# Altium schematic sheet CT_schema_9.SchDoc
size 277 x 170 mm
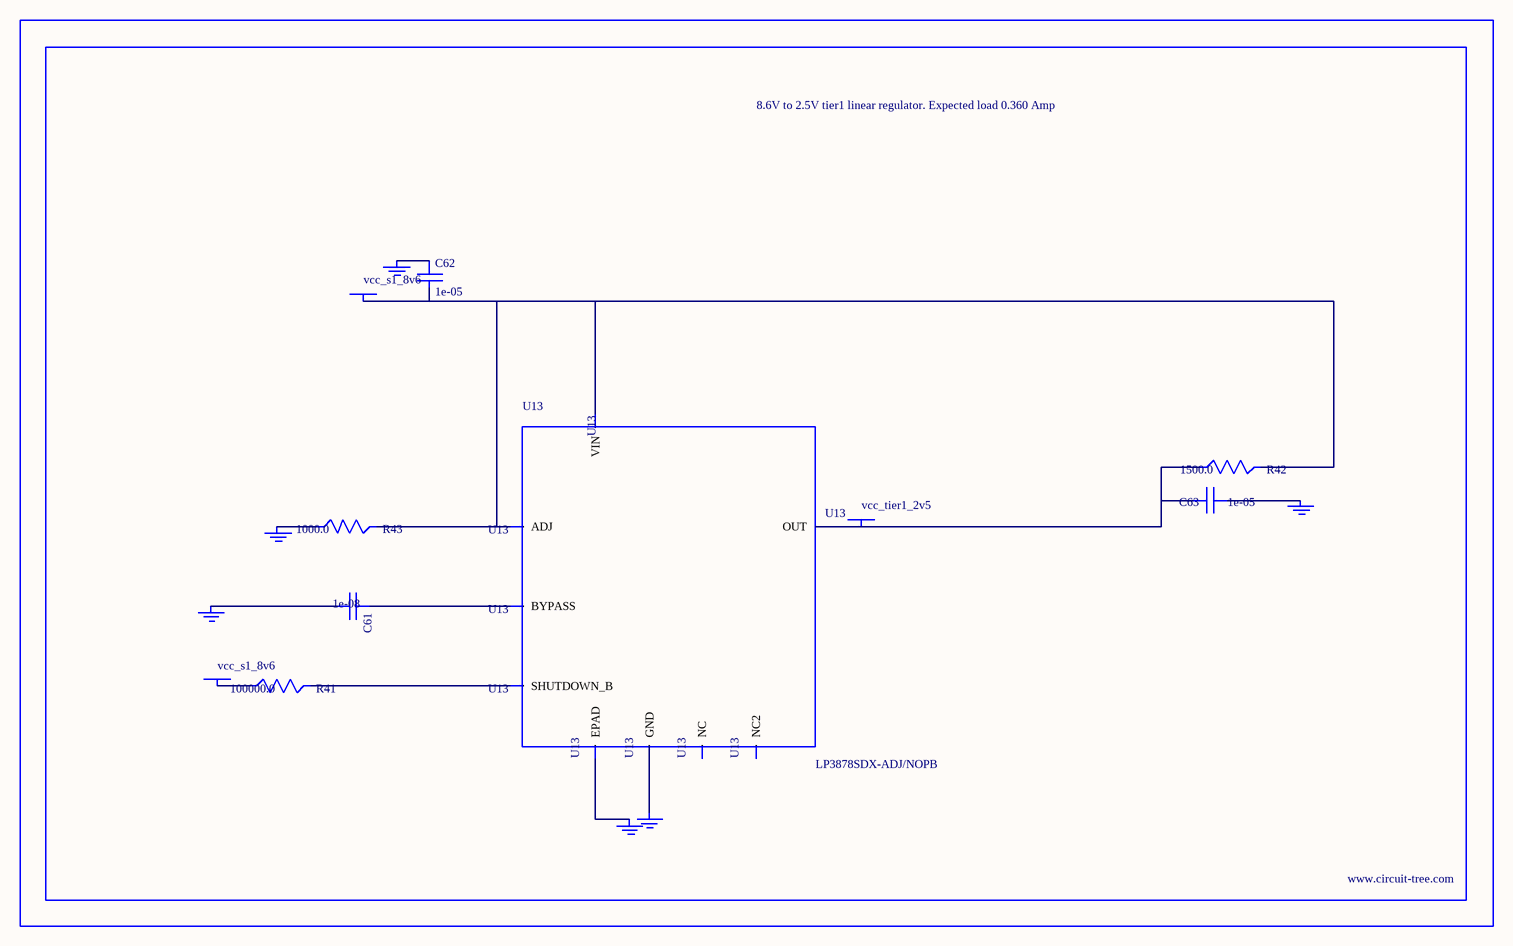
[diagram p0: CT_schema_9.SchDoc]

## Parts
BORDER8  (no value)
C61  1e-08  [C0402]
C62  1e-05  [C1206]
C63  1e-05  [C1210]
GND_INSTANCE_8_0  (no value)
GND_INSTANCE_8_1  (no value)
GND_INSTANCE_8_2  (no value)
GND_INSTANCE_8_3  (no value)
GND_INSTANCE_8_4  (no value)
GND_INSTANCE_8_5  (no value)
POWER_INSTANCE_8_0  vcc_s1_8v6
POWER_INSTANCE_8_1  vcc_s1_8v6
POWER_INSTANCE_8_2  vcc_tier1_2v5
R41  100000.0  [R0603]
R42  1500.0  [R0603]
R43  1000.0  [R0603]
U13  LP3878SDX-ADJ/NOPB  [WSON-8]

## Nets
NetC61_1: C61.1 U13.1(BYPASS)
NetC61_2: C61.2 GND_INSTANCE_8_0.0(GND)
NetC62_1: C62.1 GND_INSTANCE_8_1.0(GND)
NetC62_2: C62.2 POWER_INSTANCE_8_0.0(PWR) R42.2 R43.2 U13.4(VIN) U13.6(ADJ)
NetC63_1: C63.1 GND_INSTANCE_8_2.0(GND)
NetC63_2: C63.2 POWER_INSTANCE_8_2.0(PWR) R42.1 U13.5(OUT)
NetGND_INSTANCE_8_3_0: GND_INSTANCE_8_3.0(GND) R43.1
NetGND_INSTANCE_8_4_0: GND_INSTANCE_8_4.0(GND) U13.PAD(EPAD)
NetGND_INSTANCE_8_5_0: GND_INSTANCE_8_5.0(GND) U13.3(GND)
NetPOWER_INSTANCE_8_1_0: POWER_INSTANCE_8_1.0(PWR) R41.1
NetR41_2: R41.2 U13.8(SHUTDOWN_B)

Not connected (* = marked no-connect by the designer): U13 2(NC) 7(NC2)

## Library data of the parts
BORDER8 = BORDER_PAGE8
C61 = C0402C103K3RAC
C62 = C1206C106K3RACTU
C63 = GRM32DR61E106MA12L
GND_INSTANCE_8_0-GND_INSTANCE_8_5 = GND
POWER_INSTANCE_8_0-POWER_INSTANCE_8_2 = PWR
R41 = RC0603JR-07100KL
R42 = RC0603JR-071K5L
R43 = RC0603JR-071KL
